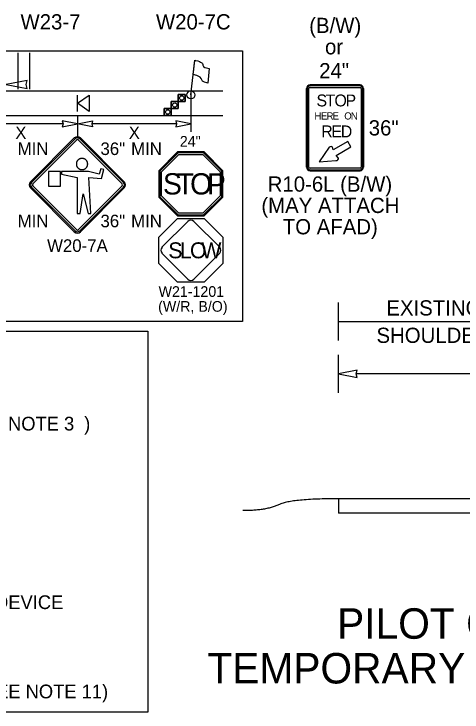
# Model space of a CAD drawing. Extents: x 99999.1 to 100095.7, y 99995 to 100010.7.
# Drawn here: x 100002.586 to 100004.94, y 100001.176 to 100004.84 of the extents above; entities that cross this region are included whole.
import ezdxf

# ---------------------------------------------------------------- set-up
doc = ezdxf.new("R2010")
doc.units = 0
for name, color, linetype in [('RD_ED_ShoulderPavedEdge', 7, 'Continuous'), ('RD_MK_LineEdgeWhite', 7, 'Continuous'), ('SH_DE_DetailHeading1Text', 7, 'Continuous'), ('TR_SN_ConstructionSigns', 7, 'Continuous'), ('TR_WZ_FlaggingStation', 7, 'Continuous'), ('TR_WZ_PortableSignMountBlk-Org', 7, 'Continuous'), ('TR_WZ_TrafficCone', 7, 'Continuous'), ('TR_WZ_WorkZoneDetails', 7, 'Continuous'), ('TR_WZ_WorkZoneTextCurrent', 7, 'Continuous')]:
    doc.layers.add(name, color=color, linetype=linetype)

msp = doc.modelspace()

# ---------------------------------------------------------------- linework, layer by layer
at = {"layer": 'RD_ED_ShoulderPavedEdge'}
msp.add_line((100000.2, 100004.3073), (100003.6825, 100004.3073), dxfattribs=at)
at = {"layer": 'RD_MK_LineEdgeWhite'}
msp.add_line((100000.2, 100004.4365), (100003.6825, 100004.4365), dxfattribs=at)
at = {"layer": 'TR_SN_ConstructionSigns'}
for p, q in [((100004.4041, 100004.4676), (100004.1416, 100004.4676)), ((100004.1416, 100004.4676), (100004.4041, 100004.4676)), ((100004.4041, 100004.4676), (100004.1416, 100004.4676)), ((100004.1229, 100004.4489), (100004.1229, 100004.0364)), ((100004.1229, 100004.0364), (100004.1229, 100004.4489)), ((100004.1229, 100004.4489), (100004.1229, 100004.0364)), ((100004.1276, 100004.4489), (100004.1276, 100004.0364)), ((100004.1354, 100004.0364), (100004.1354, 100004.4489)), ((100004.4041, 100004.4629), (100004.1416, 100004.4629)), ((100004.1416, 100004.4551), (100004.4041, 100004.4551)), ((100004.4104, 100004.4489), (100004.4104, 100004.0364)), ((100004.4182, 100004.0364), (100004.4182, 100004.4489)), ((100004.4229, 100004.0364), (100004.4229, 100004.4489)), ((100004.4229, 100004.4489), (100004.4229, 100004.0364)), ((100004.4229, 100004.0364), (100004.4229, 100004.4489)), ((100002.9031, 100004.1894), (100002.6734, 100003.9597)), ((100002.9076, 100004.1848), (100002.6779, 100003.9551)), ((100002.6843, 100003.9487), (100002.914, 100004.1784)), ((100002.9249, 100004.1784), (100003.1546, 100003.9487)), ((100003.161, 100003.9551), (100002.9313, 100004.1848)), ((100003.1656, 100003.9597), (100002.9359, 100004.1894)), ((100004.3396, 100004.1707), (100004.263, 100004.1265)), ((100004.356, 100004.1423), (100004.3396, 100004.1707)), ((100004.2424, 100004.1403), (100004.1898, 100004.0646)), ((100004.263, 100004.1265), (100004.2592, 100004.1391)), ((100004.2786, 100004.0976), (100004.356, 100004.1423)), ((100003.446, 100004.1159), (100003.3479, 100004.0178)), ((100003.4482, 100004.1107), (100003.3531, 100004.0157)), ((100003.3619, 100004.0121), (100003.4518, 100004.102)), ((100003.5847, 100004.1159), (100003.446, 100004.1159)), ((100003.5825, 100004.1107), (100003.4482, 100004.1107)), ((100003.4518, 100004.102), (100003.5789, 100004.102)), ((100003.5789, 100004.102), (100003.6688, 100004.0121)), ((100003.6775, 100004.0157), (100003.5825, 100004.1107)), ((100003.6828, 100004.0178), (100003.5847, 100004.1159)), ((100004.2909, 100004.0839), (100004.2786, 100004.0976)), ((100002.9149, 100004.0606), (100002.9145, 100004.059)), ((100002.9153, 100004.0621), (100002.9149, 100004.0606)), ((100002.9159, 100004.0636), (100002.9153, 100004.0621)), ((100002.9165, 100004.065), (100002.9159, 100004.0636)), ((100002.9171, 100004.0665), (100002.9165, 100004.065)), ((100002.9179, 100004.0679), (100002.9171, 100004.0665)), ((100002.9188, 100004.0692), (100002.9179, 100004.0679)), ((100002.9197, 100004.0705), (100002.9188, 100004.0692)), ((100002.9207, 100004.0717), (100002.9197, 100004.0705)), ((100002.9217, 100004.0729), (100002.9207, 100004.0717)), ((100002.9228, 100004.0741), (100002.9217, 100004.0729)), ((100002.924, 100004.0751), (100002.9228, 100004.0741)), ((100002.9252, 100004.0761), (100002.924, 100004.0751)), ((100002.9264, 100004.0771), (100002.9252, 100004.0761)), ((100002.9278, 100004.0779), (100002.9264, 100004.0771)), ((100002.9291, 100004.0788), (100002.9278, 100004.0779)), ((100002.9306, 100004.0795), (100002.9291, 100004.0788)), ((100002.932, 100004.0802), (100002.9306, 100004.0795)), ((100002.9335, 100004.0807), (100002.932, 100004.0802)), ((100002.935, 100004.0812), (100002.9335, 100004.0807)), ((100002.9365, 100004.0816), (100002.935, 100004.0812)), ((100002.9381, 100004.082), (100002.9365, 100004.0816)), ((100002.9396, 100004.0822), (100002.9381, 100004.082)), ((100002.9412, 100004.0824), (100002.9396, 100004.0822)), ((100002.9428, 100004.0825), (100002.9412, 100004.0824)), ((100002.9444, 100004.0825), (100002.9428, 100004.0825)), ((100002.9459, 100004.0824), (100002.9444, 100004.0825)), ((100002.9475, 100004.0822), (100002.9459, 100004.0824)), ((100002.949, 100004.082), (100002.9475, 100004.0822)), ((100002.9506, 100004.0816), (100002.949, 100004.082)), ((100002.9521, 100004.0812), (100002.9506, 100004.0816)), ((100002.9536, 100004.0807), (100002.9521, 100004.0812)), ((100002.9551, 100004.0802), (100002.9536, 100004.0807)), ((100002.9565, 100004.0795), (100002.9551, 100004.0802)), ((100002.9579, 100004.0788), (100002.9565, 100004.0795)), ((100002.9593, 100004.0779), (100002.9579, 100004.0788)), ((100002.9606, 100004.0771), (100002.9593, 100004.0779)), ((100002.9619, 100004.0761), (100002.9606, 100004.0771)), ((100002.9631, 100004.0751), (100002.9619, 100004.0761)), ((100002.9643, 100004.0741), (100002.9631, 100004.0751)), ((100002.9654, 100004.0729), (100002.9643, 100004.0741)), ((100002.9664, 100004.0717), (100002.9654, 100004.0729)), ((100002.9674, 100004.0705), (100002.9664, 100004.0717)), ((100002.9683, 100004.0692), (100002.9674, 100004.0705)), ((100002.9691, 100004.0679), (100002.9683, 100004.0692)), ((100002.9699, 100004.0665), (100002.9691, 100004.0679)), ((100002.9706, 100004.065), (100002.9699, 100004.0665)), ((100002.9712, 100004.0636), (100002.9706, 100004.065)), ((100002.9718, 100004.0621), (100002.9712, 100004.0636)), ((100002.9722, 100004.0606), (100002.9718, 100004.0621)), ((100002.9726, 100004.059), (100002.9722, 100004.0606)), ((100004.1898, 100004.0646), (100004.2776, 100004.0707)), ((100002.914, 100004.0559), (100002.9138, 100004.0543)), ((100002.9138, 100004.0543), (100002.9138, 100004.0527)), ((100002.9138, 100004.0527), (100002.9138, 100004.0512)), ((100002.9138, 100004.0512), (100002.914, 100004.0496)), ((100002.9142, 100004.0575), (100002.914, 100004.0559)), ((100002.914, 100004.0496), (100002.9142, 100004.048)), ((100002.9145, 100004.059), (100002.9142, 100004.0575)), ((100002.9142, 100004.048), (100002.9145, 100004.0465)), ((100002.9145, 100004.0465), (100002.9149, 100004.045)), ((100002.9149, 100004.045), (100002.9153, 100004.0435)), ((100002.9153, 100004.0435), (100002.9159, 100004.042)), ((100002.9159, 100004.042), (100002.9165, 100004.0405)), ((100002.9165, 100004.0405), (100002.9171, 100004.0391)), ((100002.9171, 100004.0391), (100002.9179, 100004.0377)), ((100002.9179, 100004.0377), (100002.9188, 100004.0363)), ((100002.9188, 100004.0363), (100002.9197, 100004.035)), ((100002.9197, 100004.035), (100002.9207, 100004.0338)), ((100002.9207, 100004.0338), (100002.9217, 100004.0326)), ((100002.9217, 100004.0326), (100002.9228, 100004.0315)), ((100002.9228, 100004.0315), (100002.924, 100004.0304)), ((100002.924, 100004.0304), (100002.9252, 100004.0294)), ((100002.9252, 100004.0294), (100002.9264, 100004.0284)), ((100002.9264, 100004.0284), (100002.9278, 100004.0276)), ((100002.9278, 100004.0276), (100002.9291, 100004.0268)), ((100002.9291, 100004.0268), (100002.9306, 100004.0261)), ((100002.9306, 100004.0261), (100002.932, 100004.0254)), ((100002.932, 100004.0254), (100002.9335, 100004.0248)), ((100002.9335, 100004.0248), (100002.935, 100004.0243)), ((100002.935, 100004.0243), (100002.9365, 100004.0239)), ((100002.9365, 100004.0239), (100002.9381, 100004.0236)), ((100002.949, 100004.0236), (100002.9506, 100004.0239)), ((100002.9506, 100004.0239), (100002.9521, 100004.0243)), ((100002.9521, 100004.0243), (100002.9536, 100004.0248)), ((100002.9536, 100004.0248), (100002.9551, 100004.0254)), ((100002.9551, 100004.0254), (100002.9565, 100004.0261)), ((100002.9565, 100004.0261), (100002.9579, 100004.0268)), ((100002.9579, 100004.0268), (100002.9593, 100004.0276)), ((100002.9593, 100004.0276), (100002.9606, 100004.0284)), ((100002.9606, 100004.0284), (100002.9619, 100004.0294)), ((100002.9619, 100004.0294), (100002.9631, 100004.0304)), ((100002.9631, 100004.0304), (100002.9643, 100004.0315)), ((100002.9643, 100004.0315), (100002.9654, 100004.0326)), ((100002.9654, 100004.0326), (100002.9664, 100004.0338)), ((100002.9664, 100004.0338), (100002.9674, 100004.035)), ((100002.9674, 100004.035), (100002.9683, 100004.0363)), ((100002.9683, 100004.0363), (100002.9691, 100004.0377)), ((100002.9691, 100004.0377), (100002.9699, 100004.0391)), ((100002.9699, 100004.0391), (100002.9706, 100004.0405)), ((100002.9706, 100004.0405), (100002.9712, 100004.042)), ((100002.9712, 100004.042), (100002.9718, 100004.0435)), ((100002.9718, 100004.0435), (100002.9722, 100004.045)), ((100002.9722, 100004.045), (100002.9726, 100004.0465)), ((100002.9729, 100004.0575), (100002.9726, 100004.059)), ((100002.9726, 100004.0465), (100002.9729, 100004.048)), ((100002.9731, 100004.0559), (100002.9729, 100004.0575)), ((100002.9729, 100004.048), (100002.9731, 100004.0496)), ((100002.9732, 100004.0543), (100002.9731, 100004.0559)), ((100002.9731, 100004.0496), (100002.9732, 100004.0512)), ((100002.9733, 100004.0527), (100002.9732, 100004.0543)), ((100002.9732, 100004.0512), (100002.9733, 100004.0527)), ((100003.0421, 100004.0267), (100003.0341, 100003.9996)), ((100003.0586, 100004.0237), (100003.0421, 100004.0267)), ((100004.4041, 100004.0301), (100004.1416, 100004.0301)), ((100002.7675, 100004.0137), (100002.7675, 100003.9356)), ((100002.8296, 100004.0137), (100002.7675, 100004.0137)), ((100002.8296, 100003.9356), (100002.8296, 100004.0137)), ((100002.9768, 100004.0137), (100002.8354, 100004.0137)), ((100002.8354, 100004.0137), (100002.8354, 100003.9988)), ((100002.8354, 100003.9988), (100002.9175, 100003.9825)), ((100002.9381, 100004.0236), (100002.9396, 100004.0233)), ((100002.9396, 100004.0233), (100002.9412, 100004.0231)), ((100002.9412, 100004.0231), (100002.9428, 100004.0231)), ((100002.9428, 100004.0231), (100002.9444, 100004.0231)), ((100002.9444, 100004.0231), (100002.9459, 100004.0231)), ((100002.9459, 100004.0231), (100002.9475, 100004.0233)), ((100002.9475, 100004.0233), (100002.949, 100004.0236)), ((100003.0341, 100003.9996), (100002.9768, 100004.0137)), ((100003.0462, 100003.9768), (100003.0586, 100004.0237)), ((100003.3479, 100004.0178), (100003.3479, 100003.8791)), ((100003.3531, 100004.0157), (100003.3531, 100003.8813)), ((100003.3619, 100003.8849), (100003.3619, 100004.0121)), ((100003.6688, 100004.0121), (100003.6688, 100003.8849)), ((100003.6775, 100003.8813), (100003.6775, 100004.0157)), ((100003.6828, 100003.8791), (100003.6828, 100004.0178)), ((100004.1416, 100004.0223), (100004.4041, 100004.0223)), ((100004.1416, 100004.0176), (100004.4041, 100004.0176)), ((100004.4041, 100004.0176), (100004.1416, 100004.0176)), ((100004.1416, 100004.0176), (100004.4041, 100004.0176)), ((100002.9175, 100003.9825), (100002.9175, 100003.7924)), ((100002.9902, 100003.7924), (100002.9794, 100003.9825)), ((100002.9794, 100003.9825), (100003.0462, 100003.9768)), ((100002.6734, 100003.9269), (100002.9031, 100003.6972)), ((100002.6779, 100003.9314), (100002.9076, 100003.7017)), ((100002.914, 100003.7081), (100002.6843, 100003.9378)), ((100002.7675, 100003.9356), (100002.8296, 100003.9356)), ((100003.1546, 100003.9378), (100002.9249, 100003.7081)), ((100002.9313, 100003.7017), (100003.161, 100003.9314)), ((100002.9359, 100003.6972), (100003.1656, 100003.9269)), ((100002.9341, 100003.7924), (100002.9503, 100003.897)), ((100002.9503, 100003.897), (100002.9753, 100003.7924)), ((100003.3479, 100003.8791), (100003.446, 100003.7811)), ((100003.3531, 100003.8813), (100003.4482, 100003.7863)), ((100003.4518, 100003.795), (100003.3619, 100003.8849)), ((100003.6688, 100003.8849), (100003.5789, 100003.795)), ((100003.5825, 100003.7863), (100003.6775, 100003.8813)), ((100003.5847, 100003.7811), (100003.6828, 100003.8791)), ((100002.9175, 100003.7924), (100002.9341, 100003.7924)), ((100002.9753, 100003.7924), (100002.9902, 100003.7924)), ((100003.446, 100003.7811), (100003.5847, 100003.7811)), ((100003.4482, 100003.7863), (100003.5825, 100003.7863)), ((100003.5789, 100003.795), (100003.4518, 100003.795)), ((100003.4996, 100003.7513), (100003.3637, 100003.6155)), ((100003.667, 100003.6155), (100003.5311, 100003.7513)), ((100003.3637, 100003.5839), (100003.4996, 100003.4481)), ((100003.5311, 100003.4481), (100003.667, 100003.5839))]:
    msp.add_line(p, q, dxfattribs=at)
msp.add_lwpolyline([(100003.6828, 100003.669), (100003.6828, 100003.5303), (100003.5847, 100003.4323), (100003.446, 100003.4323), (100003.3479, 100003.5303), (100003.3479, 100003.669), (100003.446, 100003.7671), (100003.5847, 100003.7671)], close=True, dxfattribs=at)
for centre, radius, start, end in [((100004.1416, 100004.4489), 0.0187, 90, 180), ((100004.1416, 100004.4489), 0.0187, 90, 180), ((100004.1416, 100004.4489), 0.0187, 90, 180), ((100004.4041, 100004.4489), 0.0187, 0, 90), ((100004.4041, 100004.4489), 0.0187, 0, 90), ((100004.4041, 100004.4489), 0.0187, 0, 90), ((100004.1416, 100004.4489), 0.0141, 90, 180), ((100004.1416, 100004.4489), 0.00625, 90, 180), ((100004.4041, 100004.4489), 0.0141, 0, 90), ((100004.4041, 100004.4489), 0.00625, 0, 90), ((100002.9195, 100004.173), 0.0232, 45, 135), ((100002.9195, 100004.173), 0.0168, 45, 135), ((100002.9195, 100004.173), 0.00773, 45, 135), ((100004.1416, 100004.0364), 0.0187, 180, 270), ((100004.1416, 100004.0364), 0.0187, 180, 270), ((100004.1416, 100004.0364), 0.0187, 180, 270), ((100004.1416, 100004.0364), 0.0141, 180, 270), ((100004.1416, 100004.0364), 0.00625, 180, 270), ((100004.4041, 100004.0364), 0.0187, 270, 0), ((100004.4041, 100004.0364), 0.0187, 270, 0), ((100004.4041, 100004.0364), 0.0187, 270, 0), ((100004.4041, 100004.0364), 0.0141, 270, 0), ((100004.4041, 100004.0364), 0.00625, 270, 0), ((100002.6898, 100003.9433), 0.0232, 135, 225), ((100002.6898, 100003.9433), 0.0168, 135, 225), ((100003.1492, 100003.9433), 0.0168, 315, 45), ((100003.1492, 100003.9433), 0.0232, 315, 45), ((100002.6898, 100003.9433), 0.00773, 135, 225), ((100003.1492, 100003.9433), 0.00773, 315, 45), ((100003.5153, 100003.7355), 0.0223, 45, 135), ((100002.9195, 100003.7136), 0.0232, 225, 315), ((100002.9195, 100003.7136), 0.0168, 225, 315), ((100002.9195, 100003.7136), 0.00773, 225, 315), ((100003.3795, 100003.5997), 0.0223, 135, 225), ((100003.6512, 100003.5997), 0.0223, 315, 45), ((100003.5153, 100003.4638), 0.0223, 225, 315)]:
    msp.add_arc(centre, radius, start, end, dxfattribs=at)
for centre, major_axis, start_param, end_param in [((100004.2492, 100004.136), (0.00934, 0.00539), 5.977036, 8.198856), ((100004.2816, 100004.0789), (-0.00913, -0.00527), 0.771965, 3.092601)]:
    msp.add_ellipse(centre, major_axis=major_axis, ratio=0.700347, start_param=start_param, end_param=end_param, dxfattribs=at)
at = {"layer": 'TR_WZ_FlaggingStation'}
for p, q in [((100003.5154, 100004.4155), (100003.5361, 100004.597)), ((100003.5277, 100004.5233), (100003.5361, 100004.5971)), ((100003.6123, 100004.5533), (100003.6037, 100004.4776)), ((100003.5277, 100004.5233), (100003.5277, 100004.5233))]:
    msp.add_line(p, q, dxfattribs=at)
for points in [[(100003.5361, 100004.5971), (100003.5398, 100004.5963), (100003.5514, 100004.5941), (100003.5603, 100004.5914), (100003.5665, 100004.5875), (100003.5721, 100004.5844), (100003.5757, 100004.58), (100003.5785, 100004.575), (100003.5788, 100004.571), (100003.5823, 100004.565), (100003.5892, 100004.5602), (100003.5973, 100004.5568), (100003.6123, 100004.5533)], [(100003.6037, 100004.4776), (100003.5985, 100004.4786), (100003.587, 100004.4816), (100003.5769, 100004.4883), (100003.5727, 100004.4952), (100003.5702, 100004.5018), (100003.5643, 100004.5089), (100003.5572, 100004.5129), (100003.546, 100004.5174), (100003.5277, 100004.5233)]]:
    msp.add_lwpolyline(points, dxfattribs=at)
msp.add_circle((100003.5154, 100004.4155), 0.021, dxfattribs=at)
at = {"layer": 'TR_WZ_PortableSignMountBlk-Org'}
msp.add_line((100002.9195, 100004.3288), (100002.9195, 100004.4149), dxfattribs=at)
msp.add_lwpolyline([(100002.9195, 100004.3718), (100002.9813, 100004.4149), (100002.9813, 100004.3288)], close=True, dxfattribs=at)
at = {"layer": 'TR_WZ_TrafficCone'}
for points in [[(100003.4491, 100004.4175), (100003.4858, 100004.4175), (100003.4858, 100004.3808), (100003.4491, 100004.3808), (100003.4491, 100004.4175)], [(100003.4491, 100004.3808), (100003.4858, 100004.3808), (100003.4858, 100004.4175), (100003.4491, 100004.4175), (100003.4491, 100004.3808)], [(100003.4123, 100004.3808), (100003.4491, 100004.3808), (100003.4491, 100004.344), (100003.4123, 100004.344), (100003.4123, 100004.3808)], [(100003.4123, 100004.344), (100003.4491, 100004.344), (100003.4491, 100004.3808), (100003.4123, 100004.3808), (100003.4123, 100004.344)], [(100003.3756, 100004.344), (100003.4123, 100004.344), (100003.4123, 100004.3073), (100003.3756, 100004.3073), (100003.3756, 100004.344)], [(100003.3756, 100004.3073), (100003.4123, 100004.3073), (100003.4123, 100004.344), (100003.3756, 100004.344), (100003.3756, 100004.3073)]]:
    msp.add_lwpolyline(points, dxfattribs=at)
for centre in [(100003.4674, 100004.3992), (100003.4307, 100004.3624), (100003.3939, 100004.3257)]:
    msp.add_circle(centre, 0.0115, dxfattribs=at)
at = {"layer": 'TR_WZ_WorkZoneDetails'}
for p, q in [((100002.6076, 100004.4465), (100002.6076, 100004.6371)), ((100002.6686, 100004.4465), (100002.6686, 100004.6371)), ((100003.5154, 100004.4365), (100003.5154, 100004.2212)), ((100002.9195, 100004.3073), (100002.9195, 100004.1962)), ((100002.8438, 100004.2642), (100002.3992, 100004.2642)), ((100003.4397, 100004.2642), (100002.9952, 100004.2642)), ((100004.2907, 100003.1255), (100004.2907, 100003.3255)), ((100004.2907, 100003.2255), (100005.2907, 100003.2255)), ((100004.2907, 100002.8515), (100004.2907, 100003.0515)), ((100006.4387, 100002.9515), (100004.3844, 100002.9515)), ((100004.2907, 100002.2954), (100004.2907, 100002.2204)), ((100008.6907, 100002.2954), (100004.2907, 100002.2954)), ((100008.6907, 100002.2204), (100004.2907, 100002.2204))]:
    msp.add_line(p, q, dxfattribs=at)
for points in [[(100002.5458, 100004.4704), (100002.655, 100004.449), (100002.6499, 100004.4704), (100002.655, 100004.4919)], [(100002.9195, 100004.2642), (100002.8401, 100004.2798), (100002.8438, 100004.2642), (100002.8401, 100004.2487)], [(100002.9195, 100004.2642), (100002.9988, 100004.2798), (100002.9952, 100004.2642), (100002.9988, 100004.2487)], [(100003.5154, 100004.2642), (100003.4361, 100004.2798), (100003.4397, 100004.2642), (100003.4361, 100004.2487)], [(100004.2907, 100002.9515), (100004.389, 100002.9322), (100004.3844, 100002.9515), (100004.389, 100002.9708)]]:
    msp.add_lwpolyline(points, close=True, dxfattribs=at)
msp.add_open_spline([(100004.2907, 100002.2954), (100004.0395, 100002.2954), (100003.914, 100002.2333), (100003.7886, 100002.2333)], degree=2, dxfattribs=at)
at = {"layer": 'TR_WZ_WorkZoneTextCurrent'}
for points in [[(100000.1, 100004.6471), (100003.7858, 100004.6471), (100003.7858, 100003.2254), (100000.1, 100003.2254)], [(100000.1, 100003.1754), (100003.2886, 100003.1754), (100003.2886, 100001.1759), (100000.1, 100001.1759)]]:
    msp.add_lwpolyline(points, close=True, dxfattribs=at)

# ---------------------------------------------------------------- texts
at = {"layer": 'SH_DE_DetailHeading1Text'}
for s, p in [('PILOT CAR OPERATION FOR ALTERNATING 1-LANE, 2-WAY TRAFFIC: AFAD-CONTROLLED +', (100004.2834, 100001.5606)), ('TEMPORARY RUMBLE STRIPS, SHARED BIKE-VEHICLE LANE STRATEGY (HIGHWAYS, 40 MPH OR LESS)', (100003.6018, 100001.3259))]:
    msp.add_text(s, height=0.16, rotation=360, dxfattribs=at).set_placement(p)
at = {"layer": 'TR_SN_ConstructionSigns'}
for s, height, p in [('W23-7', 0.08, (100002.6204, 100004.7592)), ('W20-7C', 0.08, (100003.3319, 100004.7592)), ('(B/W)', 0.08, (100004.1371, 100004.7403)), ('or', 0.08, (100004.2201, 100004.6283)), ('24"', 0.08, (100004.1895, 100004.5026)), ('36"', 0.08, (100004.4498, 100004.2026)), ('MIN', 0.066, (100002.6055, 100004.0999)), ('36"', 0.066, (100003.0405, 100004.0999)), ('MIN', 0.066, (100003.2014, 100004.0999)), ('R10-6L (B/W)', 0.08, (100003.919, 100003.9076)), ('(MAY ATTACH', 0.08, (100003.8858, 100003.7956)), ('MIN', 0.066, (100002.6055, 100003.7207)), ('36"', 0.066, (100003.0405, 100003.7207)), ('MIN', 0.066, (100003.2014, 100003.7207)), ('TO AFAD)', 0.08, (100003.9982, 100003.6836)), ('W20-7A', 0.066, (100002.76, 100003.5914)), ('W21-1201', 0.05581, (100003.3457, 100003.3555)), ('(W/R, B/O)', 0.05581, (100003.3434, 100003.2774))]:
    msp.add_text(s, height=height, rotation=360, dxfattribs=at).set_placement(p)
for s, height, p in [('S', 0.0625, (100004.1754, 100004.3551)), ('T', 0.0625, (100004.2229, 100004.3551)), ('O', 0.0625, (100004.2698, 100004.3551)), ('P', 0.0625, (100004.3279, 100004.3551)), ('H', 0.0375, (100004.1643, 100004.2864)), ('E', 0.0375, (100004.1988, 100004.2864)), ('R', 0.0375, (100004.2284, 100004.2864)), ('E', 0.0375, (100004.2603, 100004.2864)), ('O', 0.0375, (100004.3211, 100004.2864)), ('N', 0.0375, (100004.3559, 100004.2864)), ('R', 0.0625, (100004.2004, 100004.1926)), ('E', 0.0625, (100004.2535, 100004.1926)), ('D', 0.0625, (100004.3029, 100004.1926)), ('24"', 0.05581, (100003.4574, 100004.1438)), ('S', 0.1116, (100003.3686, 100003.8927)), ('T', 0.1116, (100003.4411, 100003.8927)), ('O', 0.1116, (100003.5114, 100003.8927)), ('P', 0.1116, (100003.5996, 100003.8927)), ('S', 0.0837, (100003.3969, 100003.5578)), ('L', 0.0837, (100003.458, 100003.5578)), ('O', 0.0837, (100003.5107, 100003.5578)), ('W', 0.0837, (100003.5702, 100003.5578))]:
    msp.add_text(s, height=height, dxfattribs=at).set_placement(p)
at = {"layer": 'TR_WZ_WorkZoneDetails'}
for s, p in [('EXISTING', (100004.5424, 100003.2575)), ('SHOULDER', (100004.4905, 100003.1135))]:
    msp.add_text(s, height=0.08, rotation=360, dxfattribs=at).set_placement(p)
at = {"layer": 'TR_WZ_WorkZoneTextCurrent'}
for p in [(100002.5935, 100004.1846), (100003.1894, 100004.1846)]:
    msp.add_text('X', height=0.0646, dxfattribs=at).set_placement(p)
for s, p in [('SEE NOTE 3', (100002.3354, 100002.6538)), (')', (100002.9549, 100002.6538)), ('AUTOMATED FLAGGER ASSISTANCE DEVICE', (100000.732, 100001.7165)), ('TEMP. PORTABLE RUMBLE STRIPS (SEE NOTE 11)', (100000.732, 100001.2479))]:
    msp.add_text(s, height=0.072, rotation=360, dxfattribs=at).set_placement(p)

doc.saveas('drawing.dxf')
